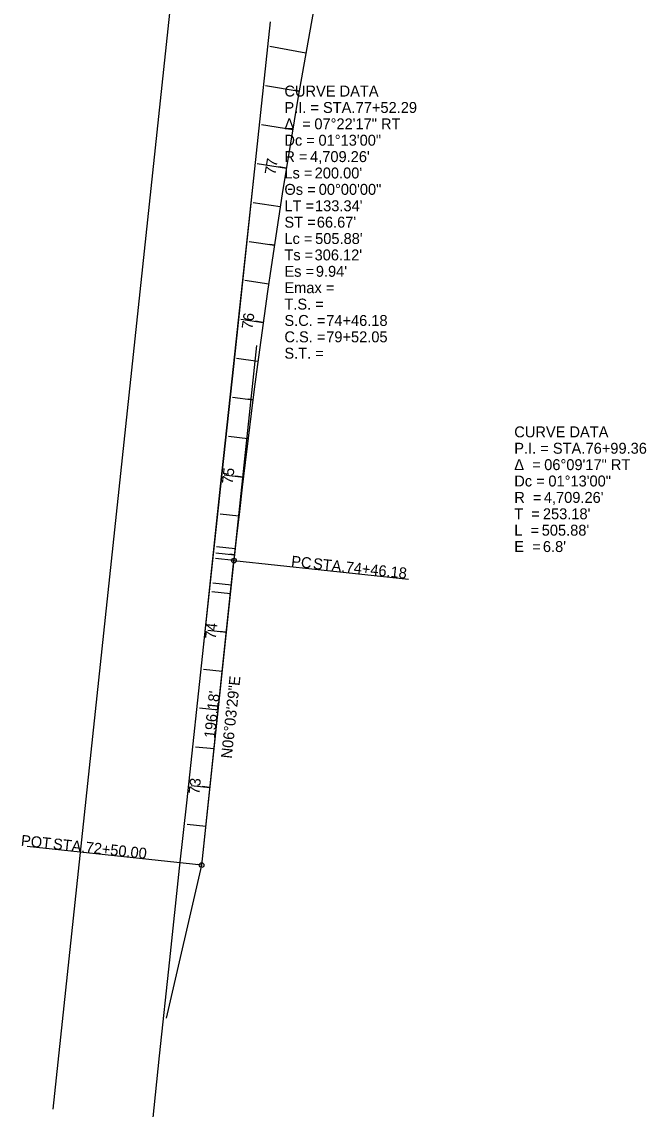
# Model space of a CAD drawing. Extents: x 172104 to 172774, y 250510 to 260293.
# Drawn here: x 172153 to 172553, y 254022 to 254719 of the extents above; entities that cross this region are included whole.
import ezdxf

# ---------------------------------------------------------------- set-up
doc = ezdxf.new("R2010")
doc.units = 0
for name, color, linetype in [('DT_P_Break_Line', 7, 'Continuous'), ('DT_P_Contour_Major', 7, 'Continuous'), ('DT_P_Contour_Minor', 7, 'Continuous'), ('DT_P_Spot_Elevations', 7, 'Continuous'), ('DT_P_Terrain_Boundary', 7, 'Continuous'), ('DT_P_Triangles', 7, 'Continuous'), ('DT_P_Void', 7, 'Continuous'), ('DT_X_Spot_Elev', 7, 'Continuous'), ('MD_P_Surface_Ditch', 7, 'Continuous')]:
    doc.layers.add(name, color=color, linetype=linetype)

msp = doc.modelspace()

# ---------------------------------------------------------------- linework, layer by layer
at = {"layer": 'DT_P_Contour_Minor'}
msp.add_line((172267.9, 254178.49), (172288.6, 254373.57), dxfattribs=at)
msp.add_arc((176971.56, 253876.57), 4709.26, 167.78705, 173.94188, dxfattribs=at)
at = {"layer": 'DT_P_Spot_Elevations'}
for p, q in [((172288.6, 254373.57), (172400.47, 254361.7)), ((172267.9, 254178.49), (172156.03, 254190.36))]:
    msp.add_line(p, q, dxfattribs=at)
for centre in [(172288.6, 254373.57), (172267.9, 254178.49)]:
    msp.add_circle(centre, 1.5, dxfattribs=at)
at = {"layer": 'DT_P_Terrain_Boundary'}
msp.add_line((172172.85, 254021.98), (172391.79, 256084.93), dxfattribs=at)
msp.add_line((172172.85, 254021.98), (172391.79, 256084.93), dxfattribs=at)
at = {"layer": 'DT_P_Triangles'}
for p, q in [((172301.3, 254618.7), (172312, 254718.91)), ((172301.36, 254618.7), (172312.06, 254718.91)), ((172288.35, 254497.98), (172301.3, 254618.7)), ((172288.41, 254497.97), (172301.36, 254618.7)), ((172267.9, 254178.49), (172303.23, 254511.37)), ((172280.04, 254421.22), (172288.35, 254497.98)), ((172280.1, 254421.22), (172288.41, 254497.97)), ((172269.04, 254318.17), (172280.04, 254421.22)), ((172269.1, 254318.16), (172280.1, 254421.22)), ((172267.9, 254178.49), (172288.6, 254373.57)), ((172258.65, 254220.18), (172269.04, 254318.17)), ((172258.71, 254220.17), (172269.1, 254318.16)), ((172253.62, 254176.4), (172258.65, 254220.18)), ((172253.68, 254176.39), (172258.71, 254220.17)), ((172245.41, 254080.31), (172267.9, 254178.49)), ((172247.49, 254117.7), (172253.62, 254176.4)), ((172247.55, 254117.69), (172253.68, 254176.39)), ((172240.9, 254056.15), (172247.49, 254117.7)), ((172240.96, 254056.14), (172247.55, 254117.69)), ((172234.56, 253994.92), (172240.9, 254056.15)), ((172234.62, 253994.91), (172240.96, 254056.14))]:
    msp.add_line(p, q, dxfattribs=at)
msp.add_arc((176971.56, 253876.57), 4709.26, 167.78705, 173.94188, dxfattribs=at)
at = {"layer": 'DT_P_Void'}
for p, q in [((172330.39, 254674.45), (172327.43, 254674.96)), ((172322.18, 254625.13), (172317.24, 254625.93)), ((172314.49, 254575.73), (172311.53, 254576.17)), ((172307.33, 254526.24), (172302.38, 254526.93)), ((172300.7, 254476.69), (172297.72, 254477.07)), ((172294.59, 254427.06), (172289.62, 254427.64)), ((172289.01, 254377.37), (172286.02, 254377.69)), ((172283.73, 254327.65), (172278.76, 254328.18)), ((172278.45, 254277.93), (172275.47, 254278.25)), ((172273.18, 254228.21), (172268.2, 254228.74)), ((172267.9, 254178.49), (172264.92, 254178.81))]:
    msp.add_line(p, q, dxfattribs=at)
at = {"layer": 'MD_P_Surface_Ditch'}
for p, q in [((172311.52, 254703.19), (172334.69, 254699.08)), ((172308.86, 254678.15), (172330.39, 254674.45)), ((172306.21, 254653.14), (172326.22, 254649.8)), ((172303.55, 254628.13), (172322.18, 254625.13)), ((172300.9, 254603.14), (172318.27, 254600.44)), ((172298.25, 254578.17), (172314.49, 254575.73)), ((172295.6, 254553.2), (172310.85, 254550.99)), ((172292.95, 254528.25), (172307.33, 254526.24)), ((172290.3, 254503.3), (172303.95, 254501.47)), ((172287.66, 254478.36), (172300.7, 254476.69)), ((172285.01, 254453.43), (172297.58, 254451.88)), ((172282.36, 254428.5), (172294.59, 254427.06)), ((172279.72, 254403.57), (172291.73, 254402.22)), ((172277.07, 254378.65), (172289.01, 254377.37)), ((172277.51, 254382.67), (172289.44, 254381.38)), ((172288.6, 254373.57), (172276.67, 254374.84)), ((172275.01, 254359.23), (172286.95, 254357.96)), ((172274.43, 254353.78), (172286.37, 254352.51)), ((172271.8, 254328.92), (172283.73, 254327.65)), ((172269.16, 254304.06), (172281.09, 254302.79)), ((172266.52, 254279.2), (172278.45, 254277.93)), ((172263.88, 254254.34), (172275.81, 254253.07)), ((172261.24, 254229.48), (172273.18, 254228.21)), ((172258.6, 254204.62), (172270.54, 254203.35))]:
    msp.add_line(p, q, dxfattribs=at)

# ---------------------------------------------------------------- texts
at = {"layer": 'DT_P_Break_Line'}
msp.add_text("196.18'", height=7, rotation=83.94188, dxfattribs=at).set_placement((172276.38, 254259.44))
at = {"layer": 'DT_P_Contour_Major'}
msp.add_text('N06°03\'29"E', height=7, rotation=83.94188, dxfattribs=at).set_placement((172287.19, 254246.52))
at = {"layer": 'DT_P_Spot_Elevations'}
for s, p in [('PC', (172325, 254369.81)), (' STA. ', (172336.4, 254368.6)), ('74+46.18', (172359.9, 254366.11)), ('POT', (172151.86, 254190.91)), (' STA. ', (172169.76, 254189.01)), ('72+50.00', (172193.26, 254186.52))]:
    msp.add_text(s, height=7, rotation=353.94188, dxfattribs=at).set_placement(p)
at = {"layer": 'DT_P_Void'}
for s, rotation, p in [('77', 80.8537, (172315.09, 254620.45)), ('76', 82.07037, (172300.37, 254521.56)), ('75', 83.28703, (172287.74, 254422.36)), ('74', 83.94188, (172276.95, 254322.96)), ('73', 83.94188, (172266.39, 254223.51))]:
    msp.add_text(s, height=7, rotation=rotation, dxfattribs=at).set_placement(p)
at = {"layer": 'DT_X_Spot_Elev'}
for s, p in [('CURVE DATA', (172320.91, 254670.98)), ('P.I. = STA. ', (172320.91, 254660.48)), ('77+52.29', (172366.58, 254660.48)), ('Δ  = ', (172320.91, 254649.98)), ('07°22\'17" RT', (172340.1, 254649.98)), ('Dc = ', (172320.91, 254639.48)), ('01°13\'00"', (172342.76, 254639.48)), ('R = ', (172320.91, 254628.98)), ("4,709.26'", (172337.37, 254628.98)), ('Ls = ', (172320.91, 254618.48)), ("200.00'", (172340.31, 254618.48)), ('Θs = ', (172320.91, 254607.98)), ('00°00\'00"', (172342.91, 254607.98)), ('LT = ', (172320.91, 254597.48)), ("133.34'", (172340.54, 254597.48)), ('ST = ', (172320.91, 254586.98)), ("66.67'", (172341.68, 254586.98)), ('Lc = ', (172320.91, 254576.48)), ("505.88'", (172340.61, 254576.48)), ('Ts = ', (172320.91, 254565.98)), ("306.12'", (172340.25, 254565.98)), ('Es = ', (172320.91, 254555.48)), ("9.94'", (172341.06, 254555.48)), ('Emax = ', (172320.91, 254544.98)), ('T.S. = ', (172320.91, 254534.48)), ('S.C. = ', (172320.91, 254523.98)), ('74+46.18', (172347.71, 254523.98)), ('C.S. = ', (172320.91, 254513.48)), ('79+52.05', (172347.71, 254513.48)), ('S.T. = ', (172320.91, 254502.98))]:
    msp.add_text(s, height=7, dxfattribs=at).set_placement(p)
for s, p in [('CURVE DATA', (172468.2, 254452.58)), ('P.I. = STA. ', (172468.2, 254442.08)), ('76+99.36', (172513.87, 254442.08)), ('Δ  = ', (172468.2, 254431.58)), ('06°09\'17" RT', (172487.39, 254431.58)), ('Dc = ', (172468.2, 254421.08)), ('01°13\'00"', (172490.05, 254421.08)), ('R  = ', (172468.2, 254410.58)), ("4,709.26'", (172487.16, 254410.58)), ('T  = ', (172468.2, 254400.08)), ("253.18'", (172486.55, 254400.08)), ('L  = ', (172468.2, 254389.58)), ("505.88'", (172485.8, 254389.58)), ('E  = ', (172468.2, 254379.08)), ("6.8'", (172486.55, 254379.08))]:
    msp.add_text(s, height=7, rotation=360, dxfattribs=at).set_placement(p)

doc.saveas('drawing.dxf')
